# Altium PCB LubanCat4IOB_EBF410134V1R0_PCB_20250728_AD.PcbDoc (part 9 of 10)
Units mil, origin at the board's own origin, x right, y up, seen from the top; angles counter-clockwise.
Board outline 5236.21 x 4055.11 mil, 6 copper layers (TOP, GND02, ART03, PWR04, GND05, BOTTOM), stack 47.2 mil thick; 614 components, 490 nets, 2311 pads, 1916 vias.
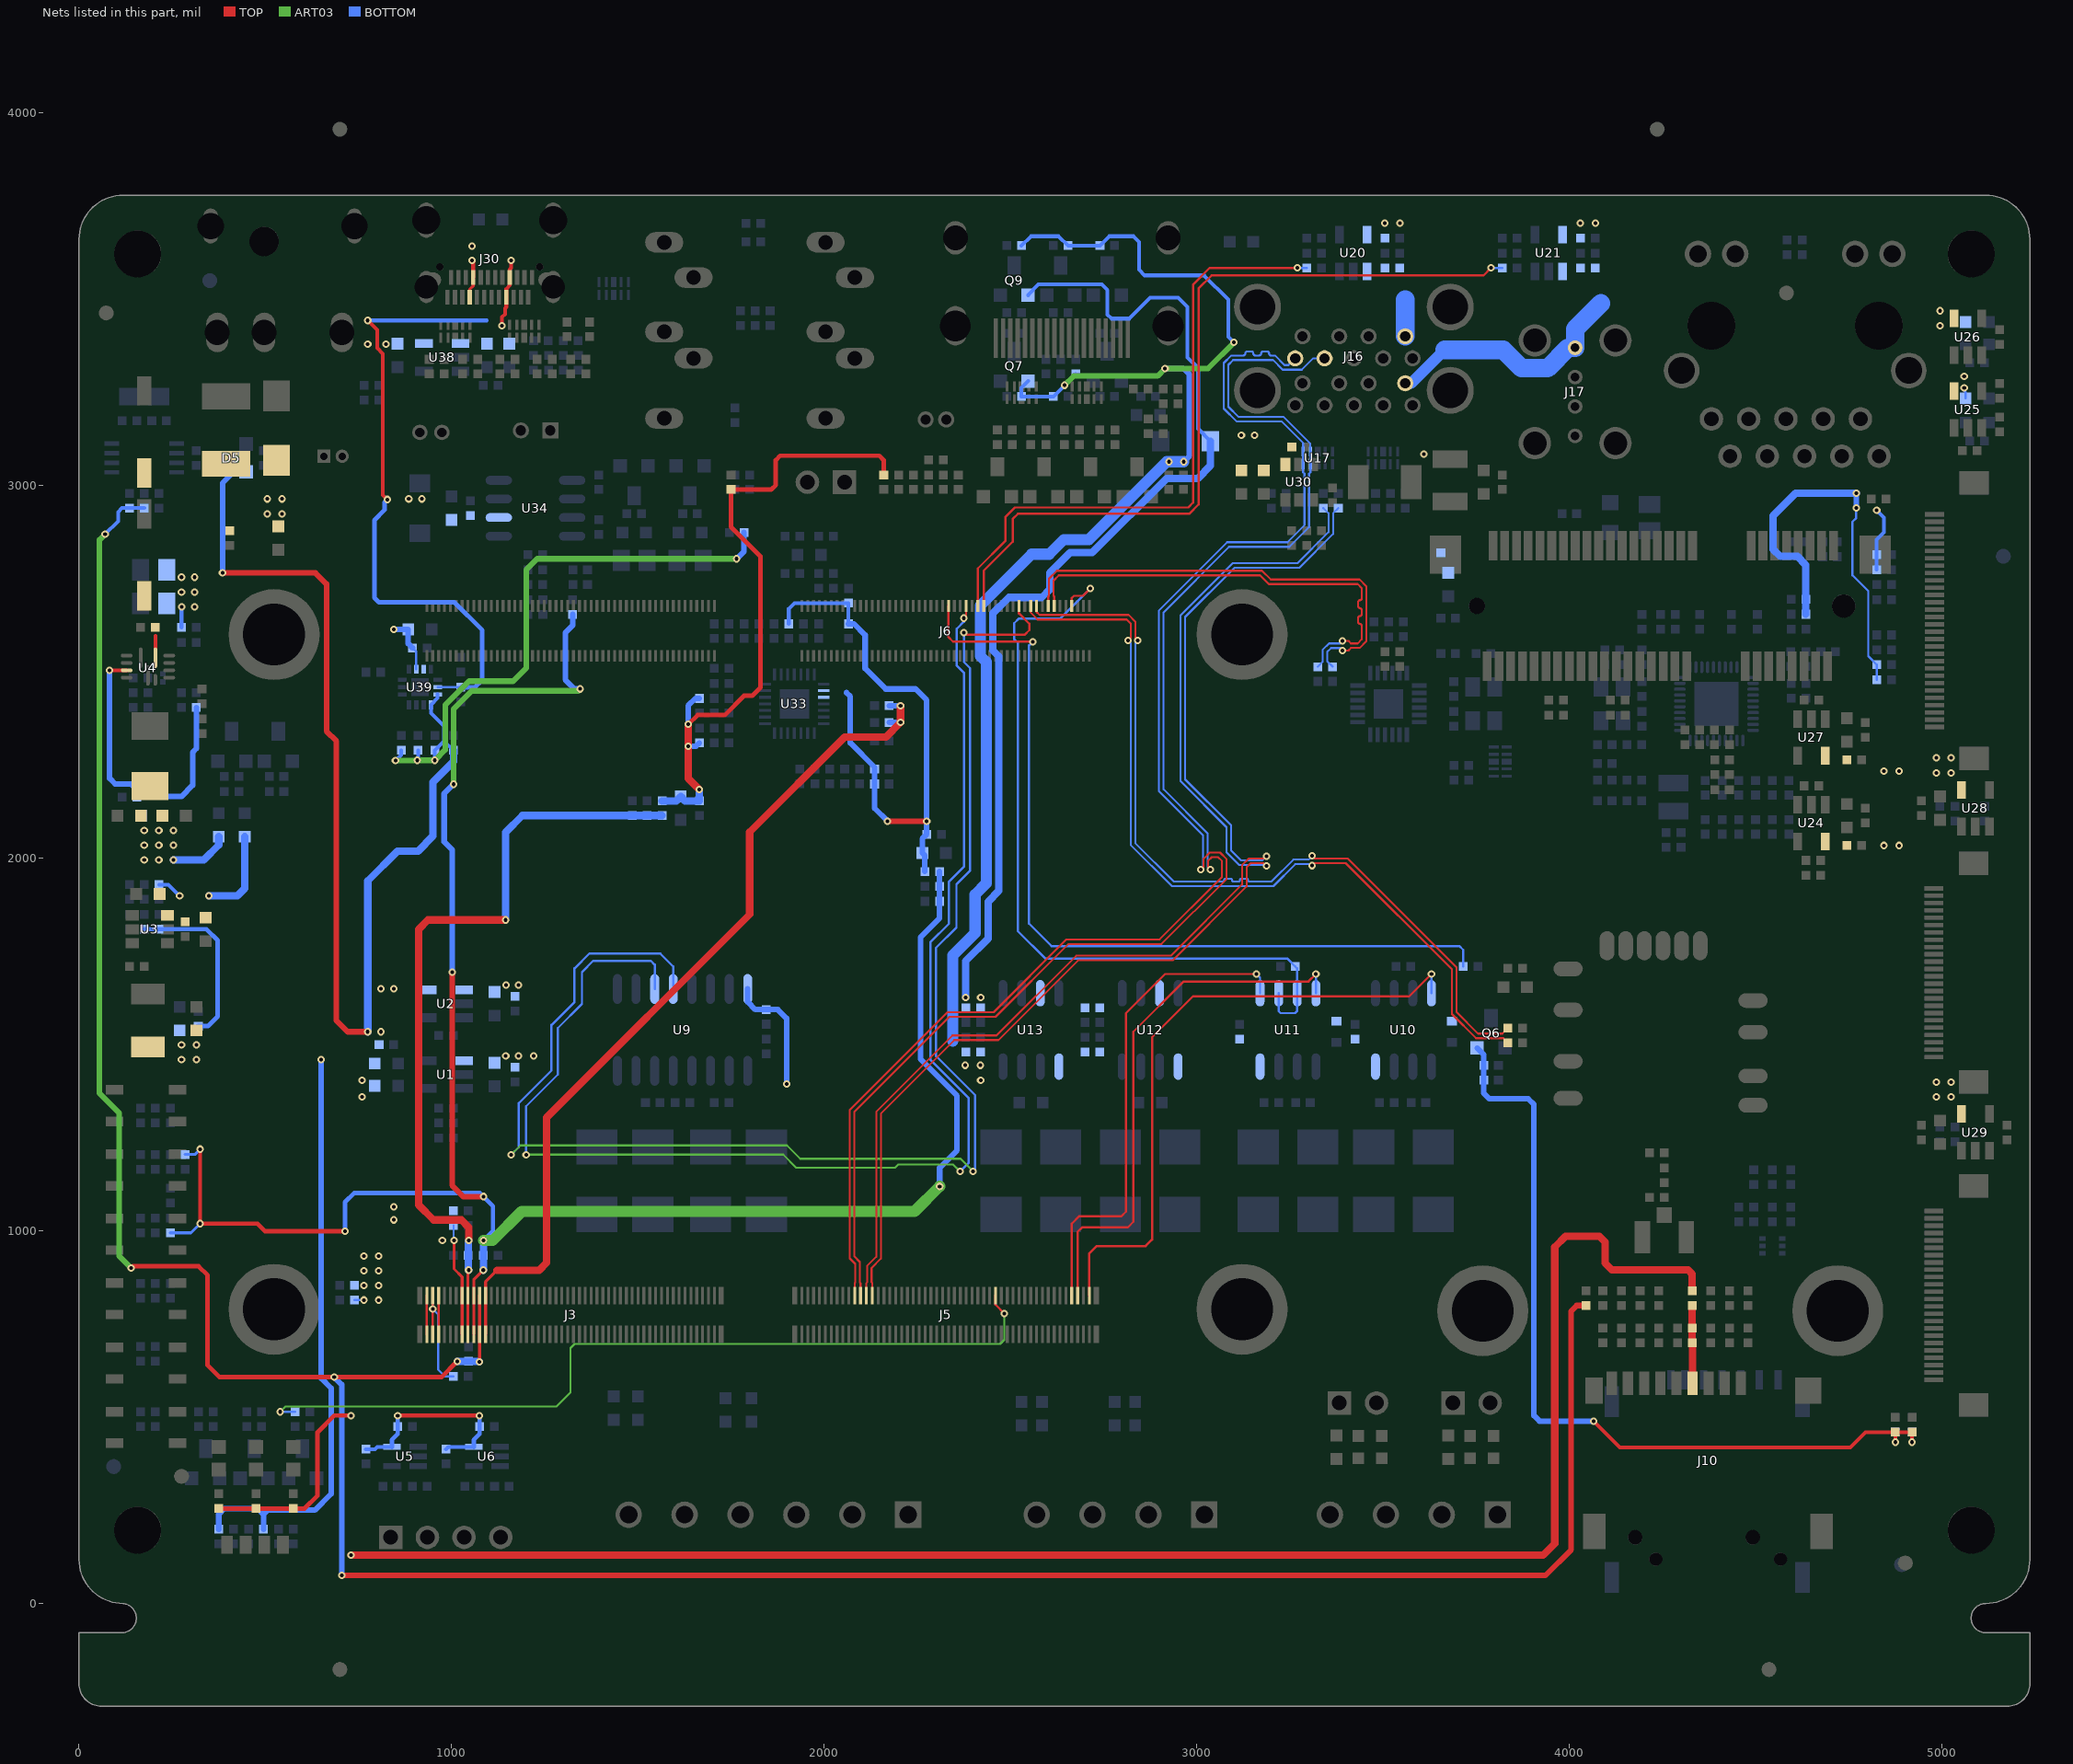
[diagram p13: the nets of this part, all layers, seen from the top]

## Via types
v1: diameter 20, hole 10, TOP to BOTTOM, 1912 vias
v2: diameter 40/50/50/50/50/40 (per signal layer), hole 0, TOP to BOTTOM, 4 vias

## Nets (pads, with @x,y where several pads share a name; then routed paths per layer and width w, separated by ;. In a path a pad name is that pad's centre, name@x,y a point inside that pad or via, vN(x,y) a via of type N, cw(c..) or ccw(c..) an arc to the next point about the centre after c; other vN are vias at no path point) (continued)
UART4_TX_M2: J5.99 U10.4 | length 1711.3
  TOP w6: J5.99@2711.81,826.59 2711.81,939.37 2731.81,959.37 2863,959.37 2880,976.37 2880,1519.37 2990,1629.37 3570,1629.37 v1(3630,1689.37)
  BOTTOM w6: U10.4@3630,1637.8 v1(3630,1689.37)
UART7_DIR: J6.94 R73.1 U11.2 U11.3 | length 2163.6
  TOP w6: J6.94@2664.56,2677.37 2664.56,2698.37 2670.56,2704.37 2694.37,2704.37 v1(2714.37,2724.37)
  BOTTOM w6: v1(2714.37,2724.37) 2633,2643 2522,2643 2510,2631 2510,2588 2520,2578 2520,1804.37 2594.2,1730.17 3243.88,1730.17 R73.1@3264.68,1709.37 3270,1704.05 U11.3@3270,1637.8 3270,1590.37 3264,1584.37 3225,1584.37 3220,1589.37 U11.2@3220,1637.8
UART7_RX_M2: J5.93 U11.1 | length 1333.4
  TOP w6: J5.93@2664.57,826.59 2664.57,1018.93 2685,1039.37 2798,1039.37 2810,1051.37 2810,1584.37 2915,1689.37 v1(3160,1689.37)
  BOTTOM w6: v1(3160,1689.37) 3170,1679.37 U11.1@3170,1637.8
UART7_TX_M2: J5.95 U11.4 | length 1447.4
  TOP w6: J5.95@2680.31,826.59 2680.31,997.37 2692.31,1009.37 2815,1009.37 2830,1024.37 2830,1534.37 2965,1669.37 3300,1669.37 v1(3320,1689.37)
  BOTTOM w6: U11.4@3320,1637.8 v1(3320,1689.37)
UART9_RX_M2: J6.76 U9.12 | length 4001.6
  TOP w6: v1(2375,2605.14) 2379.77,2600.37 2538.66,2600.37 2550.66,2612.37 2550.66,2629.34 2522.83,2657.17 J6.76@2522.83,2677.37
  ART03 w5.5: v1(1160,1204.37) 1185,1229.37 1900,1229.37 1936,1193.37 2366,1193.37 v1(2400,1159.37)
  BOTTOM w6: v1(1160,1204.37) 1180,1224.37 1180,1342.5 1268,1430.5 1268,1552.37 1330,1614.37 1330,1704.37 1370,1744.37 1560,1744.37 1594.8,1709.57 U9.12@1594.8,1649.17 ; v1(2375,2605.14) 2375,2527 2392,2510 2392,1967 2355,1930 2355,1814.37 2300,1759.37 2300,1469.37 2405,1364.37 2405,1164.37 v1(2400,1159.37)
UART9_TX_M2: J6.58 U9.11 | length 3645.5
  TOP w6: v1(2375,2644.51) 2381.09,2650.61 J6.58@2381.09,2677.37
  ART03 w5.5: v1(1200,1204.37) 1890,1204.37 1925,1169.37 2190,1169.37 2199,1178.37 2346,1178.37 v1(2365,1159.37)
  BOTTOM w6: v1(1200,1204.37) 1200,1334.37 1285,1419.37 1285,1544.37 1350,1609.37 1350,1694.37 1380,1724.37 1535,1724.37 1545.2,1714.17 U9.11@1545.2,1649.17 ; v1(2365,1159.37) 2387.6,1181.97 2387.6,1356.77 2285,1459.37 2285,1774.37 2335,1824.37 2335,1937.37 2375,1977.37 2375,2498 2356,2517 2356,2616 2375,2635 v1(2375,2644.51)
USB20_HOST0_DM: J6.88 R120.2 | length 1247.2
  TOP w5.3: J6.88@2617.32,2677.37 2617.32,2702.8 2615.59,2704.52 2615.59,2744.96 2630,2759.37 3170,2759.37 3193.61,2735.77 3432.1,2735.77 3442.7,2725.17 3442.7,2697.16 cw(c3438.05,2697.16) 3438.05,2692.51 ccw(c3438.05,2687.86) 3433.4,2687.86 3433.4,2675.96 ccw(c3438.05,2675.96) 3438.05,2671.31 cw(c3438.05,2666.66) 3442.7,2666.66 3442.7,2654.76 cw(c3438.05,2654.76) 3438.05,2650.11 ccw(c3438.05,2645.46) 3433.4,2645.46 3433.4,2633.56 ccw(c3438.05,2633.56) 3438.05,2628.91 cw(c3438.05,2624.26) 3442.7,2624.26 3442.7,2587.3 3432.1,2576.7 3413.91,2576.7 3407.06,2583.55 v1(3391.32,2583.55)
  BOTTOM w5.3: R120.2@3325,2514.05 3337.7,2526.75 3337.7,2558.86 3355.51,2576.67 3384.33,2576.67 3391.21,2583.55 v1(3391.32,2583.55)
USB20_HOST0_DP: J6.86 R119.2 | length 1267.6
  TOP w5.3: J6.86@2601.57,2677.37 2601.57,2702.8 2603.29,2704.52 2603.29,2750.06 2624.91,2771.67 3175.1,2771.67 3198.7,2748.07 3437.2,2748.07 3455,2730.26 3455,2582.21 3437.2,2564.4 3413.91,2564.4 3407.06,2557.55 v1(3391.32,2557.55)
  BOTTOM w5.3: R119.2@3365,2514.05 3350,2529.05 3350,2553.77 3360.6,2564.37 3384.5,2564.37 v1(3391.32,2557.55)
USB20_HOST1_DM: J6.82 R109.1 | length 2255.9
  TOP w5.3: J6.82@2570.07,2677.37 2570.07,2661.2 2578.3,2652.97 2817.2,2652.97 2835,2635.17 2835,2591.22 v1(2841.85,2584.37) ; v1(3310,2006.22) 3316.85,1999.37 3405,1999.37 3697.3,1707.07 3697.3,1587.07 3755,1529.37 3820.32,1529.37 R109.1@3835.32,1544.37
  BOTTOM w5.3: v1(2841.85,2584.37) 2835,2577.52 2835,2040.77 2938.4,1937.37 3069.66,1937.37 ccw(c3069.66,1941.37) 3073.66,1941.37 cw(c3077.66,1941.37) 3077.66,1945.37 3090.86,1945.37 cw(c3090.86,1941.37) 3094.86,1941.37 ccw(c3098.86,1941.37) 3098.86,1937.37 3112.05,1937.37 ccw(c3112.05,1941.37) 3116.05,1941.37 cw(c3120.05,1941.37) 3120.05,1945.37 3133.26,1945.37 cw(c3133.26,1941.37) 3137.26,1941.37 ccw(c3141.26,1941.37) 3141.26,1937.37 3200.6,1937.37 3259.6,1996.37 3300.15,1996.37 v1(3310,2006.22)
USB20_HOST1_DP: J6.80 R108.1 | length 2256
  TOP w5.3: J6.80@2554.32,2677.37 2554.32,2659.56 2573.2,2640.68 2812.1,2640.68 2822.7,2630.07 2822.7,2591.22 v1(2815.85,2584.37) ; v1(3310,1980.22) 3316.85,1987.07 3399.91,1987.07 3685,1701.97 3685,1581.97 3749.91,1517.07 3822.62,1517.07 R108.1@3835.32,1504.37
  BOTTOM w5.3: v1(2815.85,2584.37) 2822.7,2577.52 2822.7,2035.67 2933.3,1925.07 3205.7,1925.07 3264.7,1984.07 3306.15,1984.07 v1(3310,1980.22)
USB20_PWR_EN: J6.64 R124.1 | length 2198.2
  TOP w6: J6.64@2428.34,2677.37 2428.34,2771.71 2506.05,2849.42 2506.05,2910.42 2520,2924.37 2980,2924.37 3005,2949.37 3005,3529.37 3040,3564.37 3770,3564.37 v1(3790,3584.37)
  BOTTOM w6: v1(3790,3584.37) 3819.68,3584.37 R124.1@3820,3584.69
USB20_VBUS: C105.1 C106.1 J16.10 J17.1 U21.1 | length 684
  BOTTOM w30: J16.10@3559.69,3274.86 3575.49,3274.86 3665,3364.37
  BOTTOM w50: 3665,3364.37 3822.98,3364.37 3871.91,3315.45 3942.14,3315.45 3996.84,3370.15 J17.1@4015.74,3370.15 4015.74,3420.15 4084.96,3489.37
USB30_PWR_EN: J6.62 R118.1 | length 1697.3
  TOP w6: J6.62@2412.59,2677.37 2412.59,2777.96 2486.36,2851.73 2486.36,2915.73 2512,2941.37 2977,2941.37 2990,2954.37 2990,3539.37 3035,3584.37 v1(3270,3584.37)
  BOTTOM w6: v1(3270,3584.37) 3270.32,3584.69 R118.1@3295,3584.69
USB30_SSRXN: J5.21 J16.5 U17.1 U17.10 | length 3991.7
  TOP w5.3: J5.21@2097.64,826.59 2097.64,859.88 2095.91,861.61 2095.91,916.46 2080.95,931.42 2080.95,1319.32 2336,1574.37 2460,1574.37 2655.5,1769.87 2905.5,1769.87 3080.3,1944.67 3080.3,1997.57 3062.49,2015.37 3035.22,2015.37 3018.6,1998.75 3018.6,1977.12 v1(3010.85,1969.37)
  BOTTOM w5.3: v1(3010.85,1969.37) 3017.2,1975.72 3017.2,2061.17 2898.7,2179.67 2898.7,2665.07 3081.8,2848.17 3243.4,2848.17 3289.32,2894.09 3289.32,3032.37 3285.63,3036.06 U17.10@3285.63,3057.15 U17.1@3285.63,3091.59 3285.63,3114.74 3228.36,3172.01 3107.36,3172.01 3072.5,3206.87 3072.5,3329.31 3092.56,3349.37 3125.1,3349.37 ccw(c3125.1,3354.87) 3130.6,3354.87 cw(c3136.1,3354.87) 3136.1,3360.37 3146.3,3360.37 cw(c3146.3,3354.87) 3151.8,3354.87 ccw(c3157.3,3354.87) 3157.3,3349.37 3167.5,3349.37 ccw(c3167.5,3354.87) 3173,3354.87 cw(c3178.5,3354.87) 3178.5,3360.37 3188.7,3360.37 cw(c3188.7,3354.87) 3194.2,3354.87 ccw(c3199.7,3354.87) 3199.7,3349.37 3210,3349.37 3235.61,3323.76 3246.39,3323.76 J16.5@3264.39,3341.76
USB30_SSRXP: J5.19 J16.6 U17.2 U17.9 | length 3992
  TOP w5.3: J5.19@2081.89,826.59 2081.89,859.88 2083.61,861.61 2083.61,911.36 2068.65,926.33 2068.65,1324.41 2330.91,1586.67 2454.91,1586.67 2650.41,1782.17 2900.4,1782.17 3068,1949.77 3068,1992.47 3057.4,2003.07 3040.32,2003.07 3030.9,1993.65 3030.9,1975.32 v1(3036.85,1969.37)
  BOTTOM w5.3: v1(3036.85,1969.37) 3029.5,1976.72 3029.5,2066.26 2911,2184.76 2911,2659.97 3086.89,2835.87 3248.5,2835.87 3301.62,2889 3301.62,3032.37 3305.32,3036.06 U17.9@3305.32,3057.15 U17.2@3305.32,3091.59 3305.03,3091.88 3305.03,3112.73 3233.45,3184.31 3112.45,3184.31 3084.8,3211.97 3084.8,3324.21 3097.66,3337.07 3204.91,3337.07 3230.52,3311.46 3282.09,3311.46 3312.39,3341.76 J16.6@3343.19,3341.76
USB30_SSTXN: C97.2 J5.25 | length 3215.7
  TOP w5.3: J5.25@2129.13,826.59 2129.13,859.88 2127.41,861.61 2127.41,900.38 2152.3,925.27 2152.3,1314.67 2349.7,1512.07 2467.7,1512.07 2681.7,1726.07 2935.5,1726.07 3134,1924.57 3134,1975.98 3145.09,1987.07 3179.64,1987.07 v1(3187.34,1979.37)
  BOTTOM w5.3: v1(3187.34,1979.37) 3184.64,1982.07 3113.61,1982.07 3080,2015.67 3080,2083.38 2956.7,2206.68 2956.7,2652.47 3095.91,2791.67 3270.1,2791.67 3353.85,2875.42 3353.85,2925.84 C97.2@3340,2939.69
USB30_SSTXP: C98.2 J5.23 | length 3218.4
  TOP w5.3: J5.23@2113.38,826.59 2113.38,859.88 2115.11,861.61 2115.11,905.48 2140,930.37 2140,1319.77 2344.61,1524.37 2462.6,1524.37 2676.6,1738.37 2930.4,1738.37 3121.7,1929.67 3121.7,1981.07 3140,1999.37 3181.34,1999.37 v1(3187.34,2005.37)
  BOTTOM w5.3: v1(3187.34,2005.37) 3186.97,2005.37 3175.97,1994.37 3118.7,1994.37 3092.3,2020.77 3092.3,2088.47 2969,2211.77 2969,2647.37 3101,2779.37 3275.2,2779.37 3366.15,2870.32 3366.15,2925.84 C98.2@3380,2939.69
USB30_VBUS: C99.1 C101.1 J16.1 U20.1 | length 98.6
  BOTTOM w50: J16.1@3559.69,3400.86 3559.69,3499.06 3560,3499.37
USER_LED: J5.67 R39.1 | length 2262.4
  TOP w6: J5.67@2459.84,826.59 2459.84,801.99 v1(2483.46,778.37)
  ART03 w5.5: v1(540,514.37) 554.2,528.57 1281.2,528.57 1319,566.37 1319,685.37 1330,696.37 2472.46,696.37 2483.46,707.37 v1(2483.46,778.37)
  BOTTOM w6: v1(540,514.37) R39.1@580.32,514.37
VBUS_TYPEC: C196.1 C206.1 C207.1 J30.A4 J30.A9 J30.B4 J30.B9 U38.1 U39.2 | length 1974.6
  TOP w8: J30.A9@1048.42,3506.29 1048.42,3526.73 1057.87,3536.18 J30.B4@1057.87,3559.05
  TOP w10: v1(775,3443.43) 800,3418.43 800,3369.37 815,3354.37 815,2975.17 v1(827.2,2962.97) ; v1(1055,3604.37) 1057.87,3601.5 J30.B4@1057.87,3559.05 ; v1(1135,3429.37) 1135,3452.16 1143.4,3460.56 1143.4,3475.74 1146.85,3479.19 J30.A4@1146.85,3506.29 1146.85,3528.14 1156.3,3537.58 J30.B9@1156.3,3559.05 1156.3,3580.51 1160,3584.21 v1(1160,3604.37)
  BOTTOM w6: U39.2@962.64,2459.37 1024.68,2459.37 C206.1@1025,2459.05
  BOTTOM w10: v1(775,3443.43) 1094.06,3443.43
  BOTTOM w12: v1(827.2,2962.97) 820,2955.77 820,2934.57 793,2907.57 793,2699.17 805,2687.17 1007.2,2687.17 1082.4,2611.97 1082.4,2478.45 1063,2459.05 C206.1@1025,2459.05
  other v1: 1055,3643.32
VCC3V3_SYS: C10.1 C15.1 C16.1 C17.1 C132.1 C137.1 L1.2 R2.1 R6.1 U26.5 U27.5 | length 476.6
  BOTTOM w12: R6.1@175,1809.69 C10.1@215,1809.69 342,1809.69 372,1779.69 372,1575.01 346.68,1549.69 C17.1@320,1549.69
  other v1: 760,1359.37 760,1404.37 275,1459.37 315,1459.37 275,1499.37 315,1499.37 4845,2234.37 4885,2234.37 4995,3429.37 4995,3469.37
VCC5V0_SYS: C25.1 C26.1 C27.1 C28.1 C29.1 C31.1 C32.1 C107.1 C108.1 C131.1 C136.1 C189.1 C190.1 C203.1 C204.1 C205.1 J3.1 J3.2 J3.3 J3.4 J3.5 J3.6 L2.2 R11.1 R18.1 R34.1 R35.1 R36.1 R238.1 U2.5 U4.5 U20.5 U21.5 U24.5 U25.5 U28.5 U29.5 U34.6 U38.5 U39.12 U39.13 | length 2236
  TOP w6: J3.2@933.55,722.26 J3.1@933.55,826.59 ; J3.4@949.3,722.26 v1(949.3,790.37) J3.3@949.3,826.59 ; J3.6@965.05,722.26 J3.5@965.05,826.59
  TOP w10: v1(82,2504.53) U4.5@127.91,2504.53
  TOP w12: R34.1@375,254.69 R35.1@475,254.69 R36.1@575,254.69 605.32,254.69 640,289.37 640,459.37 685,504.37 v1(730,504.37)
  BOTTOM w6: C31.1@739.68,814.37 v1(765,814.37) ; C205.1@895.32,2564.37 905.16,2554.53 U39.12@905.16,2507.01 ; v1(949.3,790.37) 964,775.67 964,627.37 982,609.37 R238.1@1005.32,609.37 ; v1@5060,3265.12 v1(5060,3262.37) 5060,3254.49 5063.5,3250.99 C136.1@5063.5,3234.37
  BOTTOM w15: v1(82,2504.53) 82,2214.37 97,2199.37 139.68,2199.37 154.68,2184.37 C29.1@154.68,2164.37 ; 197,2165.69 275,2165.69 305,2195.69 305,2284.37 315,2294.37 R18.1@315,2404.69 ; v1(845,2614.37) C204.1@883.5,2614.37 883.5,2576.19 C205.1@895.32,2564.37
  BOTTOM w20: v1(253.74,1995.63) 335,1995.63 375,2035.63 R11.1@375,2057.87
  other v1: 804.37,814.37 765,853.74 804.37,853.74 765,893.11 804.37,893.11 765,932.48 804.37,932.48 4985,1359.37 5025,1359.37 4985,1399.37 5025,1399.37 810,1649.37 845,1649.37 175,1995.63 214.37,1995.63 4845,2034.37 4885,2034.37 175,2035 214.37,2035 253.74,2035 175,2074.37 214.37,2074.37 253.74,2074.37 4985,2229.37 5025,2229.37 4985,2269.37 5025,2269.37 885,2964.37 920,2964.37 5060,3293.86 775,3379.37 824.25,3379.37 3505,3704.37 3545,3704.37 4030,3704.37 4070,3704.37
VCC_1V8_S0: J3.21 J3.22 R185.1 R188.1 | length 2340.4
  TOP w8: J3.22@1091.04,722.26 J3.21@1091.04,826.59 1091.04,863.41 1122,894.37
  TOP w20: 1122,894.37 1235,894.37 1255,914.37 1255,1304.37 1800,1849.37 1800,2070.37 2055,2325.37 2166,2325.37 v1(2205,2364.37) v1(2205,2409.37)
  BOTTOM w15: R185.1@2174.68,2364.37 v1(2205,2364.37) ; R188.1@2174.68,2409.37 v1(2205,2409.37)
VCC_1V8_S3: C35.1 J3.19 J3.20 R46.1 R47.1 R61.1 | length 8112.8
  TOP w8: v1(1075,648.74) 1075.29,649.03 J3.20@1075.29,722.26 J3.19@1075.29,826.59
  TOP w12: v1(140,900) 145,905 321,905 345,881 345,639.37 377,607.37 v1(685,607.37) 973,607.37 v1(1015.32,649.69)
  TOP w15: v1(705,75.37) 3936,75.37 4005,144.37 4005,784.69 4020,799.69 R61.1@4045,799.69
  ART03 w15: v1(70,2869.37) 55,2854.37 55,1369.37 107.5,1316.87 107.5,932.5 v1(140,900)
  BOTTOM w10: v1(70,2869.37) 105,2904.37 105,2929.37 115.32,2939.69 R46.1@135,2939.69 R47.1@175,2939.69
  BOTTOM w15: v1(685,607.37) 705,587.37 v1(705,75.37)
  BOTTOM w20: v1(1015.32,649.69) C35.1@1045,649.69 1074.05,649.69 v1(1075,648.74)
VCC_3V3_S3: C11.1 C36.1 C37.1 C40.1 C42.1 C211.1 D5.2 J3.13 J3.14 R1.1 R25.1 R29.1 R56.1 R230.1 R231.1 R232.1 R233.1 U5.5 U6.5 U39.3 U39.4 | length 9913.9
  TOP w8: v1(1006.58,974.05) 1006.58,897.79 1028.04,876.33 J3.13@1028.04,826.59 J3.14@1028.04,722.26
  TOP w12: v1(855.32,504.37) v1(1075,504.37)
  TOP w15: v1(385,2766) 634.4,2766 664.4,2736 664.4,2340.97 691,2314.37 691,1564.37 721,1534.37 v1(775,1534.37)
  TOP w20: v1(730,129.37) 3930,129.37 3961,160.37 3961,956.37 3990,985.37 4080.77,985.37 4096,970.14 4096,913.37 4114,895.37 4319,895.37 4330,884.37 R56.1@4330,839.05
  ART03 w15: v1(849.3,2262.37) 907.08,2262.37 v1(907.6,2262.89) v1(955,2262.89) 983,2290.89 983,2411.37 1047,2475.37 1165,2475.37 1200,2510.37 1200,2773.74 1230,2803.74 v1(1765,2803.74)
  BOTTOM w6: C36.1@1005.32,1014.37 1005.32,975.31 v1(1006.58,974.05)
  BOTTOM w10: R25.1@770,414.05 794.68,414.05 800.91,420.28 U5.5@839.57,420.28 ; v1(849.3,2262.37) 850,2262.37 865,2277.37 R231.1@865,2289.69 ; v1(907.6,2262.89) 910,2265.29 R230.1@910,2289.69 ; v1(955,2262.89) R232.1@955,2289.69 980,2314.69 ; U39.3@962.64,2439.68 962.64,2429.84 U39.4@944.53,2411.73 944.53,2389.84 980,2354.37 980,2314.69 ; R29.1@985,414.05 991.23,420.28 U6.5@1059.57,420.28 ; C211.1@1005,2289.69 980,2314.69 ; v1(1075,504.37) v1@1075.32,504.05
  BOTTOM w12: U5.5@839.57,420.28 839.57,438.94 855.32,454.69 C40.1@855.32,474.37 v1(855.32,504.37) ; U6.5@1059.57,420.28 1059.57,438.94 1075.32,454.69 C42.1@1075.32,474.37 v1@1075.32,504.05
  BOTTOM w15: v1(385,2766) 385,3006.87 415,3036.87 D5.2@448.5,3036.87 ; v1(1765,2803.74) 1784.68,2823.42 R233.1@1784.68,2874.37
  BOTTOM w20: v1(775,1534.37) 775,1939.37 855,2019.37 910,2019.37 950,2059.37 950,2204.37 1005,2259.37 C211.1@1005,2289.69
  other v1: 975.09,974.05 845,1029.37 845,1064.37 810,1534.37
VCC_3V3_SD: C58.1 C59.1 J10.4 R56.2 | length 209.5
  TOP w20: R56.2@4330,799.69 4329.68,799.37 C58.1@4329.68,739.37 C59.1@4329.68,699.37 4330.7,698.35 J10.4@4330.7,590.75
VCC_12V: C1.1 C2.1 C3.1 C12.1 C13.1 C14.1 C19.1 C21.1 C22.1 C23.1 C147.1 C148.1 C149.1 D1.2 F1.2 R8.1 R10.1 R15.1 U3.3 U4.1 U30.3 | length 424.6
  TOP w10: U4.1@204.69,2537.99 204.69,2597.26
  BOTTOM w10: R8.1@215,1929.05 240.32,1929.05 v1(270,1899.37)
  BOTTOM w11: R15.1@275.32,2619.37 v1(275.32,2674.37)
  BOTTOM w20: v1(348.74,1899.37) 425,1899.37 445,1919.37 R10.1@445,2057.87
  other v1: 310,2674.37 275,2714.37 310,2714.37 275,2754.37 310,2754.37 505,2924.37 545,2924.37 505,2964.37 545,2964.37 3120,3135.36 3155,3135.36
VCCA1V8_CODEC: C164.1 C165.1 C174.1 C175.1 C187.1 R184.2 R200.1 R207.1 U33.2 U33.3 | length 1573.5
  TOP w15: v1(2170,2099.37) v1(2275.32,2099.37)
  BOTTOM w10: R200.1@1905,2629.05 1905,2669.37 1920.32,2684.69 R207.1@2065,2684.69 C187.1@2065,2629.05
  BOTTOM w15: 2060,2444.37 2070,2434.37 2070,2309.37 2135.32,2244.05 C175.1@2135.32,2239.37 C174.1@2135.32,2199.37 2135.32,2134.05 v1(2170,2099.37) ; C187.1@2065,2629.05 2080,2629.05 2110,2599.05 2110,2509.37 2165,2454.37 2245.32,2454.37 2275.32,2424.37 v1(2275.32,2099.37) C165.1@2275.32,2064.37 2263.5,2052.55 C164.1@2263.5,2014.37 2270.32,2007.55 R184.2@2270.32,1964.37
VCCA3V3_CODEC: C172.1 C173.1 R186.1 R187.1 R189.2 R192.2 R205.1 | length 1779.4
  TOP w12: v1(1635,2359.37) 1660,2384.37 1733,2384.37 1785,2436.37 1807,2436.37 1829,2458.37 1829,2810.37 1750,2889.37 R205.1@1750,2989.69 1858,2989.69 1870,3001.69 1870,3068.37 1882,3080.37 2148,3080.37 2160,3068.37 R192.2@2160,3029.05
  TOP w20: v1(1635,2359.37) v1(1635,2300.69) 1635,2214.37 v1(1665,2184.37)
  BOTTOM w15: v1(1635,2300.69) 1656,2300.69 R187.1@1665,2309.69 ; v1(1635,2359.37) 1635,2409.35 1654.7,2429.05 R186.1@1665,2429.05
  BOTTOM w20: R189.2@1565,2154.05 1603.18,2154.05 C172.1@1615,2165.87 1626.82,2154.05 C173.1@1665,2154.05 v1(1665,2184.37)
VCCA_1V8_S0: C34.1 C162.1 C163.1 J3.17 J3.18 R23.1 R30.2 R32.2 R184.1 | length 5799.4
  TOP w8: J3.18@1059.54,722.26 J3.17@1059.54,826.59 1059.54,869.23 v1(1085,894.69)
  TOP w10: v1(325,1019.37) v1(325,1219.37)
  TOP w12: v1(325,1019.37) 479,1019.37 499,999.37 v1(714,999.37)
  TOP w15: v1(1001.21,1694.37) 1001.21,1122.16 1031.21,1092.16 v1(1085.32,1092.16)
  ART03 w15: v1(1005,2198.74) 1005,2400.37 1054,2449.37 1339.84,2449.37 v1(1344.84,2454.37)
  ART03 w30: v1(1085.32,974.05) 1109.68,974.05 1188,1052.37 2243,1052.37 v1(2310,1119.37)
  BOTTOM w8: R30.2@245,994.69 300.32,994.69 v1(325,1019.37) ; R32.2@284.68,1205 310.63,1205 v1(325,1219.37)
  BOTTOM w12: v1(714,999.37) 714,1077.37 738,1101.37 1076.11,1101.37 v1(1085.32,1092.16) 1111,1066.48 1111,999.73 v1(1085.32,974.05)
  BOTTOM w15: v1(1001.21,1694.37) 1001.21,2023.16 980,2044.37 980,2173.74 v1(1005,2198.74) ; R23.1@1325,2654.69 1325,2625 1305,2605 1305,2479.37 1330,2454.37 v1(1344.84,2454.37) ; R184.1@2309.68,1964.37 C163.1@2309.68,1924.37 C162.1@2309.68,1884.37 2309.68,1839.05 2259,1788.37 2259,1460.37 2356.8,1362.57 2356.8,1216.17 2310,1169.37 v1(2310,1119.37)
  BOTTOM w20: v1(1085,894.69) 1085.32,895.01 C34.1@1085.32,934.37 v1(1085.32,974.05)
VCCA_3V3_S0: C33.1 C170.1 C171.1 J3.15 J3.16 R189.1 | length 2105.7
  TOP w8: J3.16@1043.79,722.26 J3.15@1043.79,826.59 1043.79,892.85 v1(1045.63,894.69)
  TOP w20: v1(1045.95,974.05) 1045.95,1009.37 1025.95,1029.37 951.6,1029.37 911.6,1069.37 911.6,1809.37 936.6,1834.37 v1(1145,1834.37)
  BOTTOM w20: v1(1045.63,894.69) 1044.68,895.64 C33.1@1044.68,934.37 1044.68,972.78 v1(1045.95,974.05) ; v1(1145,1834.37) 1145,2069.69 1190,2114.69 C170.1@1485,2114.69 C171.1@1525,2114.69 R189.1@1565,2114.69
VDD_3V3: C5.1 C6.1 C54.1 C60.1 C61.1 C62.1 C63.1 C66.1 C67.1 C90.1 C94.1 C109.1 D19.2 D23.2 Q6.2 Q7.1 R43.1 R44.1 R110.1 R126.1 R127.1 R129.1 R130.1 R132.1 R133.1 R135.1 R148.1 R150.1 R152.1 R154.1 R161.1 R162.1 R163.1 R164.1 R240.2 U1.1 U9.16 U10.8 U11.8 U12.5 U13.5 | length 9270.9
  TOP w10: v1(4065,489.37) 4136,418.37 4754,418.37 4795.32,459.69 R164.1@4875,459.69 ; v1(4875,432.89) R164.1@4875,459.69 ; v1(4920,432.89) R162.1@4920,459.69 R164.1@4875,459.69
  ART03 w15: v1(2645,3269.37) 2670,3294.37 2895,3294.37 v1(2915,3314.37) 3030,3314.37 v1(3100,3384.37)
  BOTTOM w6: v1(4770,2940) 4770,2913.07 4760,2903.07 4760,2759.83 4802.52,2717.3 4802.52,2542.17 R154.1@4825.32,2519.37 R150.1@4825.32,2479.37
  BOTTOM w10: R132.1@2529.68,3644.37 2554.68,3669.37 2629.68,3669.37 R135.1@2654.68,3644.37 R133.1@2740.32,3644.37 2765.32,3669.37 2830,3669.37 2845,3654.37 2845,3579.37 2860,3564.37 3020,3564.37 3085,3499.37 3085,3399.37 v1(3100,3384.37) ; Q7.1@2547.5,3280.87 2529.68,3263.05 R127.1@2529.68,3239.37 R129.1@2615.32,3239.37 2645,3269.05 v1(2645,3269.37) 2675,3299.37 R130.1@2675,3299.69 ; R152.1@4825.32,2774.37 R148.1@4825.32,2814.37 4825.32,2854.69 4845,2874.37 4845,2914.29 v1(4825.32,2933.97) ; v1(4875,432.89) R163.1@4875,459.69 ; v1(4920,432.89) R161.1@4920,459.69
  BOTTOM w15: R44.1@375,199.05 375,239.37 390,254.37 480,254.37 495,239.37 ; R43.1@495,199.05 495,239.37 ; v1(650,1459.37) 650,604.37 677,577.37 677,294.61 632.76,250.37 506,250.37 495,239.37 ; U9.16@1794.8,1649.17 1794.8,1614.57 1815.32,1594.05 C54.1@1845,1594.05 1875.32,1594.05 1899,1570.37 v1(1899,1394.37) ; v1(2915,3314.37) 2965,3314.37 2980,3299.37 2980,3079.37 v1(2965,3064.37) ; Q6.2@3752.5,1490.87 3770.32,1473.05 C94.1@3770.32,1444.37 R110.1@3770.32,1404.37 3770.32,1369.37 3785.32,1354.37 3890,1354.37 3905,1339.37 3905,504.37 3920,489.37 v1(4065,489.37) ; v1(4770,2940) v1(4770,2979.37)
  BOTTOM w20: R240.2@4634.68,2655 C90.1@4634.68,2695 4634.68,2787.49 4611.96,2810.21 4566.16,2810.21 4547,2829.37 4547,2918.82 4607.55,2979.37 v1(4770,2979.37)
  BOTTOM w30: 2345,1508.66 2345,1739.37 2405,1799.37 2405,1902.37 2435,1932.37 2435,2527 2419,2543 2419,2678 2557,2816 2604,2816 2643.37,2855.37 2710.63,2855.37 2919.63,3064.37 v1(2925.63,3064.37) v1(2965,3064.37)
  other v1: 2420,1404.37 2379,1444.31 2419,1444.31 1145.5,1469.37 1180,1469.37 1220,1469.37 3610,3084.37
VDD_5V: C7.1 C8.1 C64.1 C65.1 C68.1 C69.1 D28.2 Q9.1 U2.1 U12.3 U13.3 | length 2850.5
  BOTTOM w10: Q9.1@2547.5,3510.87 2547.5,3512.43 2574.94,3539.87 2745.06,3539.87 2760,3524.93 2760,3459.37 2771,3448.37 2819,3448.37 2875,3504.37 2950,3504.37 2975,3479.37 2975,3344.37 3004,3315.37 3004,3152.3 D28.2@3036.93,3119.37
  BOTTOM w20: v1(2380,1625.85) 2380,1724.37 2440,1784.37 2440,1883.37 2469,1912.37 2469,2542 2453,2558 2453,2657 2496,2700 2584,2700 2606,2722 2606,2766 2660,2820 2719.63,2820 2919,3019.37 3002.93,3019.37 3036.93,3053.37 D28.2@3036.93,3119.37
  other v1: 2420,1625.85 1146.51,1659.37 1180,1659.37
WLAN_PWR_EN: J6.52 R111.1 | length 2315.4
  TOP w6: J6.52@2333.85,2677.37 2333.85,2593.37 2345.85,2581.37 v1(2560,2581.37)
  BOTTOM w6: v1(2560,2581.37) 2550,2571.37 2550,1824.37 2610,1764.37 3705,1764.37 3715.32,1754.05 R111.1@3715.32,1709.37
pads on no net: H1.1 H2.1 H3.1 H4.1 J1. J3.25 J3.27 J3.31 J3.33 J3.35 J3.37 J3.39 J3.41 J3.43 J3.45 J3.47 J3.49 J3.53 J3.55 J3.57 J3.59 J3.61 J3.63 J3.66 J3.70 J3.72 J3.74 J3.76 J3.78 J3.80 J3.84 J3.86 J3.88 J3.90 J3.92 J3.94 J3.96 J3.98 J4.40 J4.42 J5.3 J5.5 J5.7 J5.9 J5.13 J5.15 J5.20 J5.22 J5.24 J5.26 J5.29 J5.30 J5.31 J5.32 J5.35 J5.36 J5.37 J5.38 J5.39 J5.40 J5.41 J5.42 J5.43 J5.45 J5.47 J5.49 J5.53 J5.55 J6.3 J6.4 J6.5 J6.6 J6.7 J6.9 J6.10 J6.11 J6.12 J6.13 J6.15 J6.16 J6.17 J6.18 J6.21 J6.22 J6.23 J6.24 J6.26 J6.28 J6.32 J6.34 J6.36 J6.38 J6.51 J6.53 J6.55 J6.57 J6.59 J6.61 J6.63 J6.65 J6.91 J7.1 J10. J15. J16.14 J16.15 J16.17 J16.18 J19.14 J20.14 J21.13 J21.14 J22.13 J22.14 J23.13 J23.14 J23.16 J23.17 J23.19 J23.20 J24.13 J24.14 J24.16 J24.17 J24.19 J24.20 J25. J25.3 J25.5 J25.6 J25.16 J25.17 J25.19 J25.28 J25.30 J25.32 J25.42 J25.44 J25.45 J25.46 J25.47 J25.48 J25.49 J25.51 J30. J31. J31.4 J31.6 U4.4 U15.3 U15.4 U15.9 U15.10 U15.11 U15.12 U15.13 U15.14 U19.2 U19.13 U19.17 U19.19 U19.21 U19.22 U19.23 U19.24 U32.3 U33.9 U33.25
copper on no net:
  other v2: 700,-177.16 4536.21,-177.16 700,3956.68 4236.21,3956.68

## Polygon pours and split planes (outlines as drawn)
VDD_3V3 on ART03 "ART03-VDD_3V3" (solid, pour order 85): 640,1409.37 640,1469.37 650,1479.37 2425,1479.37 2430,1474.37 2430,1379.37 2425,1374.37 1210,1374.37 1185,1399.37 650,1399.37 640,1409.37
GND on ART03 "ART03-GND" (solid, pour order 100): 50 vertices, not listed, extent 242,20 5216.21,2145.37
GND on ART03 "ART03-GND 1" (solid, pour order 87): 20 vertices, not listed, extent 4417,905.37 5149,1333.37
GND on ART03 "ART03-GND 2" (solid, pour order 84): 4554,1476.37 4297,1476.37 4144,1323.37 4144,947.37 4154,937.37 4367,937.37 4382,952.37 4382,1207.37 4401,1226.37 4561,1226.37 4571,1236.37 4571,1459.37 4554,1476.37
GND on ART03 "ART03-GND 3" (solid, pour order 93): 29 vertices, not listed, extent 280,954.37 1202,3035.37
GND on ART03 "ART03-GND 4" (solid, pour order 96): 33 vertices, not listed, extent 427,558.37 4014,1245.37
VCC_12V on ART03 "ART03-VCC_12V" (solid, pour order 92): 40 vertices, not listed, extent 495,2732.37 3165,3269.37
GND on ART03 "ART03-GND 5" (solid, pour order 81): 19 vertices, not listed, extent 2256,2802.37 3142,3151.37
GND on ART03 "ART03-GND 6" (solid, pour order 91): 44 vertices, not listed, extent 680,1751.37 2596,2892.37
GND on ART03 "ART03-GND 7" (solid, pour order 98): 43 vertices, not listed, extent 365,2960.37 4850,3550.37
GND on ART03 "ART03-GND 8" (solid, pour order 97): 66 vertices, not listed, extent 20,20 1503,3759.52
GND on ART03 "ART03-GND 9" (solid, pour order 89): 26 vertices, not listed, extent 3736,1785.37 5035,2280.37
GND on ART03 "ART03-GND 10" (solid, pour order 90): 2793,1609.37 3889,1609.37 3922,1576.37 3922,1367.37 3897,1342.37 2451,1342.37 2443,1350.37 2443,1471.37 2474,1502.37 2562,1502.37 2588,1528.37 2740,1528.37 2779,1567.37 2779,1595.37 2793,1609.37
GND on ART03 "ART03-GND 11" (solid, pour order 94): 30 vertices, not listed, extent 1434,3412.37 5216.21,3759.52
VCC3V3_SYS on ART03 "ART03-VCC3V3_SYS" (solid, pour order 99): 56 vertices, not listed, extent 205,1449.37 5197,3724.37
VDD_5V on ART03 "ART03-VDD_5V" (solid, pour order 80): 18 vertices, not listed, extent 1135,1569.37 2430,1669.37
GND on ART03 "ART03-GND 12" (solid, pour order 88): 21 vertices, not listed, extent 650,2913.37 2565,3354.37
VCC5V0_SYS on BOTTOM "BOTTOM-VCC5V0_SYS" (solid, pour order 60): 52 vertices, not listed, extent 143,1984.37 264,2175.37
VCC3V3_SYS on BOTTOM "BOTTOM-VCC3V3_SYS" (solid, pour order 11): 4990,3479.37 5005,3479.37 5025,3459.37 5075,3459.37 5080,3454.37 5080,3424.37 5075,3419.37 4990,3419.37 4985,3424.37 4985,3474.37 4990,3479.37
VCC_3V3_S3 on BOTTOM "BOTTOM-VCC_3V3_S3" (solid, pour order 77): 28 vertices, not listed, extent 720,119.37 1018,1074.37
VCC5V0_SYS on BOTTOM "BOTTOM-VCC5V0_SYS 1" (solid, pour order 22): 3445,3714.37 3445,3649.37 3515,3649.37 3520,3654.37 3520,3689.37 3525,3694.37 3550,3694.37 3555,3699.37 3555,3714.37 3550,3719.37 3450,3719.37 3445,3714.37
VCC5V0_SYS on BOTTOM "BOTTOM-VCC5V0_SYS 2" (solid, pour order 13): 82 vertices, not listed, extent 5038,3208.37 5088,3304.37
VDD_5V on BOTTOM "BOTTOM-VDD_5V" (solid, pour order 62): 36 vertices, not listed, extent 2365,1544.37 2915,1674.37
VCC3V3_SYS on BOTTOM "BOTTOM-VCC3V3_SYS 1" (solid, pour order 38): 250,1559.37 250,1454.37 255,1449.37 330,1449.37 335,1454.37 335,1559.37 330,1564.37 255,1564.37 250,1559.37
3V3_DVDD_PHY on BOTTOM "BOTTOM-3V3_DVDD_PHY" (solid, pour order 14): 4270,2629.37 4300,2629.37 4300,2514.37 4310,2504.37 4310,2484.37 4305,2479.37 4280,2479.37 4270,2489.37 4270,2629.37
GND on BOTTOM "BOTTOM-GND" (solid, pour order 12): 4625,2629.37 4670,2629.37 4690,2609.37 4690,2544.37 4685,2539.37 4660,2539.37 4655,2544.37 4655,2569.37 4620,2604.37 4620,2624.37 4625,2629.37
N17466585 on BOTTOM "BOTTOM-N17466585" (solid, pour order 34): 4240,2179.37 4320,2179.37 4321,2180.37 4321,2242.37 4328,2249.37 4328,2330.37 4326,2332.37 4299,2332.37 4296,2329.37 4296,2280.37 4240,2224.37 4240,2179.37
GND on BOTTOM "BOTTOM-GND 1" (solid, pour order 26): 2670,1574.37 2750,1574.37 2755,1569.37 2755,1509.37 2750,1504.37 2665,1504.37 2660,1509.37 2660,1564.37 2670,1574.37
VCC_3V3_S3 on BOTTOM "BOTTOM-VCC_3V3_S3 1" (solid, pour order 23): 765,1539.37 765,1434.37 770,1429.37 815,1429.37 820,1434.37 820,1539.37 815,1544.37 770,1544.37 765,1539.37
USB20_VBUS on BOTTOM "BOTTOM-USB20_VBUS" (solid, pour order 46): 3970,3599.37 4105,3599.37 4110,3594.37 4110,3474.37 4105,3469.37 4060,3469.37 4055,3474.37 4055,3544.37 4050,3549.37 3975,3549.37 3970,3554.37 3970,3599.37
GND on BOTTOM "BOTTOM-GND 2" (solid, pour order 53): 34 vertices, not listed, extent 3320,3549.37 3585,3684.37
VCC5V0_SYS on BOTTOM "BOTTOM-VCC5V0_SYS 3" (solid, pour order 21): 3970,3714.37 3970,3649.37 4040,3649.37 4045,3654.37 4045,3689.37 4050,3694.37 4075,3694.37 4080,3699.37 4080,3714.37 4075,3719.37 3975,3719.37 3970,3714.37
GND on BOTTOM "BOTTOM-GND 3" (solid, pour order 30): 2365,1574.37 2455,1574.37 2460,1569.37 2460,1509.37 2455,1504.37 2365,1504.37 2360,1509.37 2360,1569.37 2365,1574.37
1V05_PHY on BOTTOM "BOTTOM-1V05_PHY" (solid, pour order 41): 4240,2149.37 4320,2149.37 4320,2104.37 4320,2059.37 4315,2054.37 4275,2054.37 4245,2054.37 4180,2054.37 4175,2059.37 4175,2094.37 4180,2099.37 4235,2099.37 4240,2104.37 4240,2149.37
VCC5V0_SYS on BOTTOM "BOTTOM-VCC5V0_SYS 4" (solid, pour order 47): 1158,2932.37 1162,2928.37 1162,2906.37 1158,2902.37 1058,2902.37 1045,2889.37 970,2889.37 945,2914.37 880,2914.37 875,2919.37 875,2969.37 880,2974.37 938,2974.37 980,2932.37 1158,2932.37
GND on BOTTOM "BOTTOM-GND 4" (solid, pour order 83): 4554,1476.37 4297,1476.37 4144,1323.37 4144,947.37 4154,937.37 4367,937.37 4382,952.37 4382,1207.37 4401,1226.37 4561,1226.37 4571,1236.37 4571,1459.37 4554,1476.37
VCCA1V8_CODEC on BOTTOM "BOTTOM-VCCA1V8_CODEC" (solid, pour order 3): 1983,2454.37 2070,2454.37 2075,2449.37 2075,2434.37 2072.5,2431.87 2021.5,2431.87 2018,2428.37 1983,2428.37 1983,2454.37
5V0_CAM0/1 on BOTTOM "BOTTOM-5V0_CAM0/1" (solid, pour order 73): 18 vertices, not listed, extent 4950,1459.37 5175,1934.37
USB30_VBUS on BOTTOM "BOTTOM-USB30_VBUS" (solid, pour order 45): 3445,3599.37 3580,3599.37 3585,3594.37 3585,3469.37 3580,3464.37 3535,3464.37 3535,3544.37 3530,3549.37 3525,3549.37 3445,3549.37 3445,3599.37
N15118646 on BOTTOM "BOTTOM-N15118646" (solid, pour order 19): 845,1474.37 955,1474.37 960,1469.37 960,1444.37 880,1444.37 875,1439.37 875,1374.37 840,1374.37 840,1469.37 845,1474.37
VCC5V0_SYS on BOTTOM "BOTTOM-VCC5V0_SYS 5" (solid, pour order 28): 765,3364.37 945,3364.37 950,3369.37 950,3394.37 945,3399.37 765,3399.37 760,3394.37 760,3369.37 765,3364.37
3V3_WLAN on BOTTOM "BOTTOM-3V3_WLAN" (solid, pour order 27): 3770,1544.37 3770,1599.37 3775,1604.37 3875,1604.37 3880,1599.37 3880,1549.37 3875,1544.37 3770,1544.37
GND on BOTTOM "BOTTOM-GND 5" (solid, pour order 1): 4475,1004.37 4490,1004.37 4495,999.37 4495,944.37 4490,939.37 4475,939.37 4470,944.37 4470,999.37 4475,1004.37
MINIPCIE_3V3 on BOTTOM "BOTTOM-MINIPCIE_3V3" (solid, pour order 69): 30 vertices, not listed, extent 3935,2569.37 4255,2964.37
3V3_DVDD_PHY on BOTTOM "BOTTOM-3V3_DVDD_PHY 1" (solid, pour order 4): 4338,2332.37 4357,2332.37 4360,2329.37 4360,2237.37 4357,2234.37 4341,2234.37 4335,2240.37 4335,2329.37 4338,2332.37
5V0_IMAGE0 on BOTTOM "BOTTOM-5V0_IMAGE0" (solid, pour order 57): 21 vertices, not listed, extent 4955,2879.37 5085,3185.37
FAN on BOTTOM "BOTTOM-FAN" (solid, pour order 39): 354,2279.37 354,2110.37 359,2105.37 461,2105.37 461,2137.37 409,2137.37 402,2144.37 402,2269.37 392,2279.37 354,2279.37
GND on BOTTOM "BOTTOM-GND 6" (solid, pour order 7): 4180,2044.37 4330,2044.37 4335,2039.37 4335,2024.37 4330,2019.37 4180,2019.37 4175,2024.37 4175,2039.37 4180,2044.37
VCC3V3_SYS on BOTTOM "BOTTOM-VCC3V3_SYS 2" (solid, pour order 15): 820,1399.37 820,1349.37 815,1344.37 770,1344.37 755,1344.37 750,1349.37 750,1399.37 750,1409.37 755,1414.37 815,1414.37 820,1409.37 820,1399.37
VCC5V0_SYS on BOTTOM "BOTTOM-VCC5V0_SYS 6" (solid, pour order 20): 795,1664.37 960,1664.37 965,1659.37 965,1634.37 960,1629.37 795,1629.37 790,1634.37 790,1659.37 795,1664.37
GND on BOTTOM "BOTTOM-GND 7" (solid, pour order 33): 4480,1104.37 4480,1054.37 4485,1049.37 4605,1049.37 4610,1054.37 4610,1104.37 4605,1109.37 4485,1109.37 4480,1104.37
VCC5V0_SYS on BOTTOM "BOTTOM-VCC5V0_SYS 7" (solid, pour order 18): 19 vertices, not listed, extent 835,2495.37 931,2630.37
GND on BOTTOM "BOTTOM-GND 8" (solid, pour order 105): 82 vertices, not listed, extent 20,20 5216.21,3759.52
VBUS_TYPEC on BOTTOM "BOTTOM-VBUS_TYPEC" (solid, pour order 71): 1000,3369.37 1070,3369.37 1075,3364.37 1175,3364.37 1175,3604.37 1130,3649.37 1045,3649.37 1040,3644.37 1040,3514.37 1075,3479.37 1075,3399.37 1070,3394.37 1000,3394.37 1000,3369.37
VCC5V0_SYS on BOTTOM "BOTTOM-VCC5V0_SYS 8" (solid, pour order 40): 815,941.37 815,810.37 807,802.37 728,802.37 728,866.37 746,866.37 755,875.37 755,943.37 760,948.37 808,948.37 815,941.37
5V0_CAM2/3 on BOTTOM "BOTTOM-5V0_CAM2/3" (solid, pour order 74): 17 vertices, not listed, extent 4950,593.23 5190,1073.23
3V3_DVDD_PHY on BOTTOM "BOTTOM-3V3_DVDD_PHY 2" (solid, pour order 29): 19 vertices, not listed, extent 4490,2574.37 4610,2667
HUB_3V3 on BOTTOM "BOTTOM-HUB_3V3" (solid, pour order 32): 20 vertices, not listed, extent 3630,2534.37 3695,2719.37
GND on BOTTOM "BOTTOM-GND 9" (solid, pour order 54): 34 vertices, not listed, extent 3845,3549.37 4110,3684.37
VDD_3V3 on BOTTOM "BOTTOM-VDD_3V3" (solid, pour order 43): 1010,1444.37 1080,1444.37 1100,1424.37 1220,1424.37 1230,1434.37 1230,1474.37 1225,1479.37 1010,1479.37 1005,1474.37 1005,1449.37 1010,1444.37
VDD_3V3 on BOTTOM "BOTTOM-VDD_3V3 1" (solid, pour order 79): 83 vertices, not listed, extent 2330,1394.37 3770,1584.37
VDD_3V3 on BOTTOM "BOTTOM-VDD_3V3 2" (solid, pour order 52): 18 vertices, not listed, extent 3600,2744.37 3695,3099.37
3V3_IMAGE0 on BOTTOM "BOTTOM-3V3_IMAGE0" (solid, pour order 72): 34 vertices, not listed, extent 4890,2839.37 5087,3399.37
GND on BOTTOM "BOTTOM-GND 10" (solid, pour order 36): 4180,2639.37 4295,2639.37 4300,2644.37 4300,2694.37 4295,2699.37 4155,2699.37 4145,2689.37 4145,2674.37 4180,2639.37
VCC_12V on BOTTOM "BOTTOM-VCC_12V" (solid, pour order 56): 210,2804.37 210,2654.37 215,2649.37 315,2649.37 320,2654.37 320,2799.37 315,2804.37 210,2804.37
VDD_5V on BOTTOM "BOTTOM-VDD_5V 1" (solid, pour order 37): 1010,1634.37 1075,1634.37 1095,1614.37 1185,1614.37 1190,1619.37 1190,1669.37 1185,1674.37 1015,1674.37 1010,1669.37 1010,1634.37
5V0_CAM0/1 on TOP "TOP-5V0_CAM0/1" (solid, pour order 66): 23 vertices, not listed, extent 4930,1874.37 5105,2124.37
VCC5V0_SYS on TOP "TOP-VCC5V0_SYS" (solid, pour order 44): 26 vertices, not listed, extent 4675,1974.37 4895,2069.37
VCC_12V on TOP "TOP-VCC_12V" (solid, pour order 86): 45 vertices, not listed, extent 155,1819.37 566,3109.37
1V05_DVDD_PHY on TOP "TOP-1V05_DVDD_PHY" (solid, pour order 31): 18 vertices, not listed, extent 4375,2169.37 4478,2319.37
MINIPCIE_3V3 on TOP "TOP-MINIPCIE_3V3" (solid, pour order 76): 21 vertices, not listed, extent 3550,2889.37 3995,3054.37
VCC5V0_SYS on TOP "TOP-VCC5V0_SYS 1" (solid, pour order 65): 141,2231.37 141,1994.37 150,1985.37 257,1985.37 266,1994.37 266,2076.37 257,2085.37 246,2085.37 239,2092.37 239,2231.37 141,2231.37
VCC_3V3_S3 on TOP "TOP-VCC_3V3_S3" (solid, pour order 16): 973,961.37 982,961.37 990,953.37 990,899.37 1017,872.37 1027,872.37 1032,877.37 1032,979.37 1025,986.37 972,986.37 965,979.37 965,969.37 973,961.37
3V3_IMAGE1 on TOP "TOP-3V3_IMAGE1" (solid, pour order 55): 4809.37,2437.37 5006,2437.37 5006,2405.37 4848,2405.37 4838,2395.37 4838,2358.37 4827,2347.37 4677,2347.37 4675,2349.37 4675,2397.37 4676,2398.37 4786,2398.37 4796,2408.37 4796,2424 4809.37,2437.37
N17592129 on TOP "TOP-N17592129" (solid, pour order 49): 19 vertices, not listed, extent 3260,2963.37 3462,3074.37
VCC_12V on TOP "TOP-VCC_12V 1" (solid, pour order 58): 3105,3024.37 3205,3024.37 3210,3029.37 3210,3034.37 3215,3039.37 3250,3039.37 3250,3079.37 3255,3084.37 3265,3084.37 3270,3089.37 3270,3139.37 3265,3144.37 3110,3144.37 3105,3139.37 3105,3024.37
VBUS_TYPEC on TOP "TOP-VBUS_TYPEC" (solid, pour order 2): 1040,3649.37 1040,3599.37 1045,3594.37 1070,3594.37 1075,3599.37 1075,3649.37 1070,3654.37 1045,3654.37 1040,3649.37
3V3_IMAGE0 on TOP "TOP-3V3_IMAGE0" (solid, pour order 17): 82 vertices, not listed, extent 4982,3323.37 5050,3398.37
N03633 on TOP "TOP-N03633" (solid, pour order 5): 124,1786.37 160,1786.37 160,1759.37 147,1746.37 147,1697.37 124,1697.37 124,1786.37
N03641 on TOP "TOP-N03641" (solid, pour order 50): 20 vertices, not listed, extent 139,1607.37 256,1823.37
GND on TOP "TOP-GND" (solid, pour order 82): 4554,1476.37 4297,1476.37 4147,1326.37 4147,953 4160,940 4365,940 4379,954 4379,1204.37 4401,1226.37 4561,1226.37 4571,1236.37 4571,1459.37 4554,1476.37
VCC3V3_SYS on TOP "TOP-VCC3V3_SYS" (solid, pour order 9): 82 vertices, not listed, extent 4982,3417.37 5050,3481.37
MINIPCIE_3V3 on TOP "TOP-MINIPCIE_3V3 1" (solid, pour order 8): 4210,2599.37 4245,2599.37 4255,2589.37 4255,2574.37 4250,2569.37 4240,2569.37 4235,2564.37 4235,2479.37 4230,2474.37 4210,2474.37 4205,2479.37 4205,2594.37 4210,2599.37
GND on TOP "TOP-GND 1" (solid, pour order 104): 82 vertices, not listed, extent 20,20 5216.21,3759.52
3V3_DVDD_PHY on TOP "TOP-3V3_DVDD_PHY" (solid, pour order 70): 47 vertices, not listed, extent 4255,2229.37 4560,2599.37
VCC3V3_SYS on TOP "TOP-VCC3V3_SYS 1" (solid, pour order 78): 25 vertices, not listed, extent 140,1342.37 773,1554.37
1V05_PHY on TOP "TOP-1V05_PHY" (solid, pour order 48): 20 vertices, not listed, extent 4175,2079.37 4445,2199.37
5V0_IMAGE0 on TOP "TOP-5V0_IMAGE0" (solid, pour order 6): 82 vertices, not listed, extent 4997,3119.37 5047,3182.37
VCC5V0_SYS on TOP "TOP-VCC5V0_SYS 2" (solid, pour order 10): 82 vertices, not listed, extent 5015,3226.37 5071,3304.37
N18211692 on TOP "TOP-N18211692" (solid, pour order 0): 318,2426.37 318,2362.37 342,2362.37 342,2426.37 318,2426.37
5V0_IMAGE1 on TOP "TOP-5V0_IMAGE1" (solid, pour order 64): 20 vertices, not listed, extent 4675,2119.37 5010,2399.37
VCC3V3_SYS on TOP "TOP-VCC3V3_SYS 2" (solid, pour order 42): 20 vertices, not listed, extent 4675,2205.37 4895,2299.37
5V0_CAM2/3 on TOP "TOP-5V0_CAM2/3" (solid, pour order 63): 25 vertices, not listed, extent 4930,1008.23 5105,1258.23
N02088 on TOP "TOP-N02088" (solid, pour order 67): 331,3205.37 331,3446.37 347,3462.37 415,3462.37 431,3446.37 431,3287.37 443,3275.37 460,3275.37 460,3205.37 331,3205.37
N18211553 on TOP "TOP-N18211553" (solid, pour order 59): 23 vertices, not listed, extent 130,2314.37 342,2494.37
GND on TOP "TOP-GND 2" (solid, pour order 35): 4895,634.37 5000,634.37 5010,624.37 5010,574.37 5000,564.37 4895,564.37 4885,574.37 4885,624.37 4895,634.37
VCC5V0_SYS on TOP "TOP-VCC5V0_SYS 3" (solid, pour order 24): 19 vertices, not listed, extent 4975,2159.37 5065,2279.37
VCC_3V3_S3 on TOP "TOP-VCC_3V3_S3 1" (solid, pour order 68): 875,1024.37 875,1544.37 870,1549.37 770,1549.37 760,1539.37 760,1514.37 770,1504.37 815,1504.37 825,1494.37 825,1449.37 825,1024.37 830,1019.37 870,1019.37 875,1024.37
GND on TOP "TOP-GND 3" (solid, pour order 61): 32 vertices, not listed, extent 4890,1159.37 5190,1409.37
VCC5V0_SYS on TOP "TOP-VCC5V0_SYS 4" (solid, pour order 75): 954,934.37 954,896.37 969,881.37 969,698.37 930,698.37 930,748.37 920,758.37 758,758.37 745,771.37 745,807.37 745,933.37 759,947.37 941,947.37 954,934.37
VCC5V0_SYS on TOP "TOP-VCC5V0_SYS 5" (solid, pour order 25): 19 vertices, not listed, extent 4975,1289.37 5065,1409.37
3V3_WLAN on TOP "TOP-3V3_WLAN" (solid, pour order 51): 18 vertices, not listed, extent 3825,1584.37 4040,1729.37
GND on GND05 "GND05-GND" (solid, pour order 106): 82 vertices, not listed, extent 20,20 5216.21,3759.52
GND on PWR04 "PWR04-GND" (solid, pour order 103): 82 vertices, not listed, extent 20,20 5216.21,3759.52
VCC5V0_SYS on PWR04 "PWR04-VCC5V0_SYS" (solid, pour order 101): 51 vertices, not listed, extent 60,203.37 5176.21,3719.52
VDD_3V3 on PWR04 "PWR04-VDD_3V3" (solid, pour order 95): 20 vertices, not listed, extent 2289.6,2761.37 4927,3134.37
GND on GND02 "GND02-GND" (solid, pour order 102): 82 vertices, not listed, extent 20,20 5216.21,3759.52

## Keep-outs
TOP:
  region: 4623.35,3517.37 4621.97,3527.81 4617.94,3537.54 4611.53,3545.9 4603.17,3552.31 4593.44,3556.34 4583,3557.72 4572.56,3556.34 4562.83,3552.31 4554.47,3545.9 4548.06,3537.54 4544.03,3527.81 4542.65,3517.37 4544.03,3506.93 4548.06,3497.2 4554.47,3488.84 4562.83,3482.43 4572.56,3478.4 4583,3477.02 4593.44,3478.4 4603.17,3482.43 4611.53,3488.84 4617.94,3497.2 4621.97,3506.93 4623.35,3517.37
  region: 4276.56,3956.68 4275.18,3967.13 4271.15,3976.86 4264.74,3985.21 4256.38,3991.62 4246.65,3995.66 4236.21,3997.03 4225.77,3995.66 4216.04,3991.62 4207.68,3985.21 4201.27,3976.86 4197.24,3967.13 4195.86,3956.68 4197.24,3946.24 4201.27,3936.51 4207.68,3928.16 4216.04,3921.74 4225.77,3917.71 4236.21,3916.34 4246.65,3917.71 4256.38,3921.74 4264.74,3928.16 4271.15,3936.51 4275.18,3946.24 4276.56,3956.68
  region: 4576.56,-177.16 4575.18,-166.72 4571.15,-156.99 4564.74,-148.64 4556.38,-142.22 4546.65,-138.19 4536.21,-136.82 4525.77,-138.19 4516.04,-142.22 4507.68,-148.64 4501.27,-156.99 4497.24,-166.72 4495.86,-177.16 4497.24,-187.61 4501.27,-197.34 4507.68,-205.69 4516.04,-212.1 4525.77,-216.14 4536.21,-217.51 4546.65,-216.14 4556.38,-212.1 4564.74,-205.69 4571.15,-197.34 4575.18,-187.61 4576.56,-177.16
  region: 4942.35,108.37 4940.97,118.81 4936.94,128.54 4930.53,136.9 4922.17,143.31 4912.44,147.34 4902,148.72 4891.56,147.34 4881.83,143.31 4873.47,136.9 4867.06,128.54 4863.03,118.81 4861.65,108.37 4863.03,97.93 4867.06,88.2 4873.47,79.84 4881.83,73.43 4891.56,69.4 4902,68.02 4912.44,69.4 4922.17,73.43 4930.53,79.84 4936.94,88.2 4940.97,97.93 4942.35,108.37
  region: 1928,2699.37 1928,2522.37 2729,2522.37 2729,2699.37 1928,2699.37
  region: 315.35,341.37 313.97,351.81 309.94,361.54 303.53,369.9 295.17,376.31 285.44,380.34 275,381.72 264.56,380.34 254.83,376.31 246.47,369.9 240.06,361.54 236.03,351.81 234.65,341.37 236.03,330.93 240.06,321.2 246.47,312.84 254.83,306.43 264.56,302.4 275,301.02 285.44,302.4 295.17,306.43 303.53,312.84 309.94,321.2 313.97,330.93 315.35,341.37
  region: 740.35,-177.16 738.97,-166.72 734.94,-156.99 728.53,-148.64 720.17,-142.22 710.44,-138.19 700,-136.82 689.56,-138.19 679.83,-142.22 671.47,-148.64 665.06,-156.99 661.03,-166.72 659.65,-177.16 661.03,-187.61 665.06,-197.34 671.47,-205.69 679.83,-212.1 689.56,-216.14 700,-217.51 710.44,-216.14 720.17,-212.1 728.53,-205.69 734.94,-197.34 738.97,-187.61 740.35,-177.16
  region: 1102,856.37 1102,692.37 1742,692.37 1742,856.37 1102,856.37
  region: 1899,856.37 1899,692.37 2748,692.37 2748,856.37 1899,856.37
  region: 924,2699.37 924,2522.37 1717,2522.37 1717,2699.37 924,2699.37
  region: 113.35,3463.37 111.97,3473.81 107.94,3483.54 101.53,3491.9 93.17,3498.31 83.44,3502.34 73,3503.72 62.56,3502.34 52.83,3498.31 44.47,3491.9 38.06,3483.54 34.03,3473.81 32.65,3463.37 34.03,3452.93 38.06,3443.2 44.47,3434.84 52.83,3428.43 62.56,3424.4 73,3423.02 83.44,3424.4 93.17,3428.43 101.53,3434.84 107.94,3443.2 111.97,3452.93 113.35,3463.37
  region: 740.35,3956.68 738.97,3967.13 734.94,3976.86 728.53,3985.21 720.17,3991.62 710.44,3995.66 700,3997.03 689.56,3995.66 679.83,3991.62 671.47,3985.21 665.06,3976.86 661.03,3967.13 659.65,3956.68 661.03,3946.24 665.06,3936.51 671.47,3928.16 679.83,3921.74 689.56,3917.71 700,3916.34 710.44,3917.71 720.17,3921.74 728.53,3928.16 734.94,3936.51 738.97,3946.24 740.35,3956.68
GND02:
  region: 4225.42,1001.37 4225.1,1003.97 4225,1006.37 4225,1089.37 4225.11,1091.99 4225.32,1093.75 4225.32,1168.9 4225.32,1169.05 4225.32,1196.62 4225,1196.94 4225,1232.37 4225.45,1242.56 4226.78,1252.67 4228.98,1262.63 4232.05,1272.36 4235.96,1281.78 4240.66,1290.83 4246.15,1299.43 4252.35,1307.52 4259.24,1315.04 4344.63,1400.42 4354.6,1409.56 4365.33,1417.79 4376.73,1425.06 4388.73,1431.31 4401.23,1436.48 4414.12,1440.55 4427.33,1443.47 4440.73,1445.24 4454.25,1445.83 4520,1445.83 4522.61,1445.72 4525.21,1445.37 4527.76,1444.81 4530.26,1444.02 4532.68,1443.02 4535,1441.81 4537.21,1440.4 4539.28,1438.81 4541.21,1437.04 4542.98,1435.11 4544.57,1433.04 4545.98,1430.83 4547.19,1428.51 4548.19,1426.09 4548.98,1423.59 4549.54,1421.04 4549.89,1418.44 4550,1415.83 4549.89,1413.22 4549.54,1410.62 4548.98,1408.07 4548.19,1405.57 4547.19,1403.15 4545.98,1400.83 4544.57,1398.62 4542.98,1396.55 4541.21,1394.62 4539.28,1392.85 4537.21,1391.26 4535,1389.85 4532.68,1388.64 4530.26,1387.64 4527.76,1386.85 4525.21,1386.29 4522.61,1385.94 4520,1385.83 4454.25,1385.83 4445.96,1385.47 4437.75,1384.39 4429.65,1382.59 4421.75,1380.1 4414.09,1376.93 4406.73,1373.1 4399.74,1368.65 4393.17,1363.6 4387.06,1358 4301.67,1272.61 4298.32,1268.95 4295.29,1265.01 4292.63,1260.83 4290.33,1256.42 4288.43,1251.84 4286.94,1247.1 4285.86,1242.25 4285.22,1237.33 4285,1232.37 4285,1213.42 4285.27,1210.82 4285.32,1209 4285.32,1089.69 4285.21,1087.08 4285,1085.32 4285,1006.37 4284.89,1003.75 4284.58,1001.37 4225.42,1001.37
BOTTOM:
  region: 4932.35,104.37 4930.97,114.81 4926.94,124.54 4920.53,132.9 4912.17,139.31 4902.44,143.34 4892,144.72 4881.56,143.34 4871.83,139.31 4863.47,132.9 4857.06,124.54 4853.03,114.81 4851.65,104.37 4853.03,93.93 4857.06,84.2 4863.47,75.84 4871.83,69.43 4881.56,65.4 4892,64.02 4902.44,65.4 4912.17,69.43 4920.53,75.84 4926.94,84.2 4930.97,93.93 4932.35,104.37
  region: 4276.56,3956.68 4275.18,3967.13 4271.15,3976.86 4264.74,3985.21 4256.38,3991.62 4246.65,3995.66 4236.21,3997.03 4225.77,3995.66 4216.04,3991.62 4207.68,3985.21 4201.27,3976.86 4197.24,3967.13 4195.86,3956.68 4197.24,3946.24 4201.27,3936.51 4207.68,3928.16 4216.04,3921.74 4225.77,3917.71 4236.21,3916.34 4246.65,3917.71 4256.38,3921.74 4264.74,3928.16 4271.15,3936.51 4275.18,3946.24 4276.56,3956.68
  region: 391.35,3550.37 389.97,3560.81 385.94,3570.54 379.53,3578.9 371.17,3585.31 361.44,3589.34 351,3590.72 340.56,3589.34 330.83,3585.31 322.47,3578.9 316.06,3570.54 312.03,3560.81 310.65,3550.37 312.03,3539.93 316.06,3530.2 322.47,3521.84 330.83,3515.43 340.56,3511.4 351,3510.02 361.44,3511.4 371.17,3515.43 379.53,3521.84 385.94,3530.2 389.97,3539.93 391.35,3550.37
  region: 5205.35,2810.37 5203.97,2820.81 5199.94,2830.54 5193.53,2838.9 5185.17,2845.31 5175.44,2849.34 5165,2850.72 5154.56,2849.34 5144.83,2845.31 5136.47,2838.9 5130.06,2830.54 5126.03,2820.81 5124.65,2810.37 5126.03,2799.93 5130.06,2790.2 5136.47,2781.84 5144.83,2775.43 5154.56,2771.4 5165,2770.02 5175.44,2771.4 5185.17,2775.43 5193.53,2781.84 5199.94,2790.2 5203.97,2799.93 5205.35,2810.37
  region: 4576.56,-177.16 4575.18,-166.72 4571.15,-156.99 4564.74,-148.64 4556.38,-142.22 4546.65,-138.19 4536.21,-136.82 4525.77,-138.19 4516.04,-142.22 4507.68,-148.64 4501.27,-156.99 4497.24,-166.72 4495.86,-177.16 4497.24,-187.61 4501.27,-197.34 4507.68,-205.69 4516.04,-212.1 4525.77,-216.14 4536.21,-217.51 4546.65,-216.14 4556.38,-212.1 4564.74,-205.69 4571.15,-197.34 4575.18,-187.61 4576.56,-177.16
  region: 740.35,-177.16 738.97,-166.72 734.94,-156.99 728.53,-148.64 720.17,-142.22 710.44,-138.19 700,-136.82 689.56,-138.19 679.83,-142.22 671.47,-148.64 665.06,-156.99 661.03,-166.72 659.65,-177.16 661.03,-187.61 665.06,-197.34 671.47,-205.69 679.83,-212.1 689.56,-216.14 700,-217.51 710.44,-216.14 720.17,-212.1 728.53,-205.69 734.94,-197.34 738.97,-187.61 740.35,-177.16
  region: 133.35,367.37 131.97,377.81 127.94,387.54 121.53,395.9 113.17,402.31 103.44,406.34 93,407.72 82.56,406.34 72.83,402.31 64.47,395.9 58.06,387.54 54.03,377.81 52.65,367.37 54.03,356.93 58.06,347.2 64.47,338.84 72.83,332.43 82.56,328.4 93,327.02 103.44,328.4 113.17,332.43 121.53,338.84 127.94,347.2 131.97,356.93 133.35,367.37
  region: 740.35,3956.68 738.97,3967.13 734.94,3976.86 728.53,3985.21 720.17,3991.62 710.44,3995.66 700,3997.03 689.56,3995.66 679.83,3991.62 671.47,3985.21 665.06,3976.86 661.03,3967.13 659.65,3956.68 661.03,3946.24 665.06,3936.51 671.47,3928.16 679.83,3921.74 689.56,3917.71 700,3916.34 710.44,3917.71 720.17,3921.74 728.53,3928.16 734.94,3936.51 738.97,3946.24 740.35,3956.68
Multi-Layer:
  region: 4290.54,3019.68 4290.54,3449.37 4925,3449.37 4925,3019.68 4290.54,3019.68

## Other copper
TOP:
  drawing of 242 lines, arcs and shapes, not listed
GND02:
  drawing of 627 lines, arcs and shapes, not listed
ART03:
  drawing of 284 lines, arcs and shapes, not listed
PWR04:
  drawing of 1578 lines, arcs and shapes, not listed
GND05:
  drawing of 626 lines, arcs and shapes, not listed
BOTTOM:
  drawing of 271 lines, arcs and shapes, not listed

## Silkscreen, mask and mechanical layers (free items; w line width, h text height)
DESIGN_OUTLINE:
  lines w1: 0,118.11 ccw(c118.11,118.11) 118.11,0 5118.1,0 ccw(c5118.1,118.11) 5236.21,118.11 5236.21,3661.41 ccw(c5118.1,3661.41) 5118.1,3779.52 118.11,3779.52 ccw(c118.11,3661.41) 0,3661.41 0,118.11
  lines w5.91: 118.11,-78.74 ccw(c113.95,-39.37) 118.11,0 ; 5118.1,-78.74 cw(c5118.1,-39.37) 5118.1,0
  lines w6: 118.11,-78.74 0,-78.74 0,-215.59 ccw(c60,-215.59) 60,-275.59 5176.21,-275.59 ccw(c5176.21,-215.59) 5236.21,-215.59 5236.21,-78.74 5118.1,-78.74
PLACE_BOUND_TOP:
  region: 235,301.37 315,301.37 315,381.37 235,381.37
  region: 33,3423.37 113,3423.37 113,3503.37 33,3503.37
  region: 4543,3477.37 4623,3477.37 4623,3557.37 4543,3557.37
  region: 4862,68.37 4942,68.37 4942,148.37 4862,148.37
  region: 660,3916.68 740,3916.68 740,3996.68 660,3996.68
  region: 4196.21,3916.68 4276.21,3916.68 4276.21,3996.68 4196.21,3996.68
  region: 4496.21,-217.16 4576.21,-217.16 4576.21,-137.16 4496.21,-137.16
  region: 660,-217.16 740,-217.16 740,-137.16 660,-137.16
PLACE_BOUND_BOTTOM:
  region: 391,3510.37 391,3590.37 311,3590.37 311,3510.37 391,3510.37
  region: 5205,2770.37 5205,2850.37 5125,2850.37 5125,2770.37 5205,2770.37
  region: 4932,64.37 4932,144.37 4852,144.37 4852,64.37 4932,64.37
  region: 133,327.37 133,407.37 53,407.37 53,327.37 133,327.37
  region: 740,3916.68 740,3996.68 660,3996.68 660,3916.68 740,3916.68
  region: 4276.21,3916.68 4276.21,3996.68 4196.21,3996.68 4196.21,3916.68 4276.21,3916.68
  region: 4576.21,-217.16 4576.21,-137.16 4496.21,-137.16 4496.21,-217.16 4576.21,-217.16
  region: 740,-217.16 740,-137.16 660,-137.16 660,-217.16 740,-217.16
